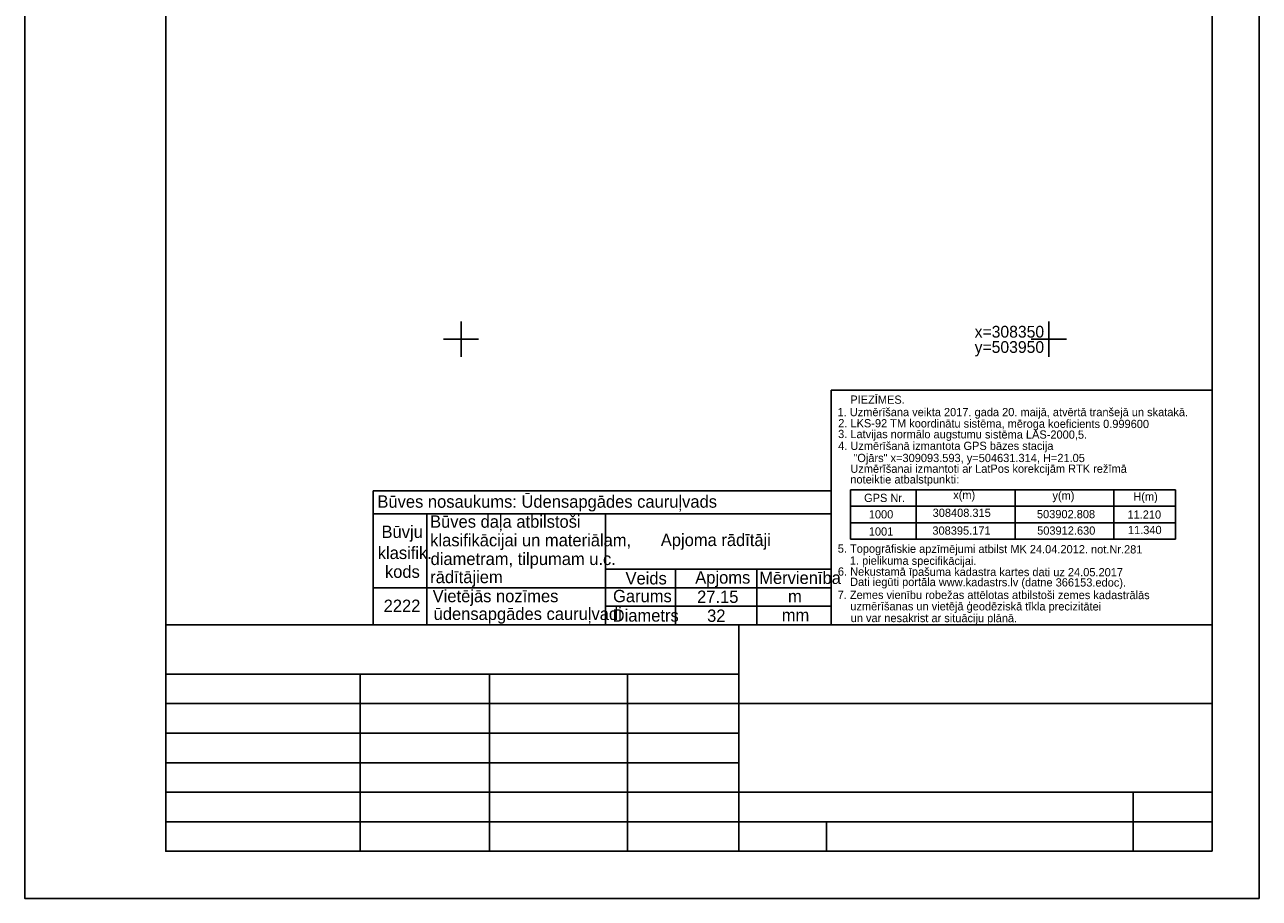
# Model space of a CAD drawing. Extents: x 503863 to 503968, y 308302 to 308451.
# Drawn here: x 503862.9 to 503967.9, y 308302.5 to 308376.7 of the extents above; entities that cross this region are included whole.
import ezdxf

# ---------------------------------------------------------------- set-up
doc = ezdxf.new("R2010")
doc.units = 0
for name, color, linetype in [('GEOD_ELEM_####_####_#', 7, 'Continuous'), ('GEOD_KORD_####_TKST_#', 7, 'Continuous'), ('RAMI_PLAN_####_TKST_#', 7, 'Continuous')]:
    doc.layers.add(name, color=color, linetype=linetype)

msp = doc.modelspace()

# ---------------------------------------------------------------- linework, layer by layer
at = {"layer": 'GEOD_ELEM_####_####_#'}
for p, q in [((503900, 308351.5), (503900, 308350)), ((503950, 308351.5), (503950, 308350)), ((503898.5, 308350), (503900, 308350)), ((503900, 308350), (503900, 308348.5)), ((503900, 308350), (503901.5, 308350)), ((503948.5, 308350), (503950, 308350)), ((503950, 308350), (503950, 308348.5)), ((503950, 308350), (503951.5, 308350))]:
    msp.add_line(p, q, dxfattribs=at)
at = {"layer": 'RAMI_PLAN_####_TKST_#'}
for p, q in [((503963.89, 308443.52), (503963.89, 308306.47)), ((503931.47, 308345.66), (503931.47, 308325.71)), ((503931.47, 308345.66), (503963.89, 308345.66)), ((503931.47, 308325.71), (503931.47, 308340.26)), ((503892.54, 308337.11), (503892.54, 308325.71)), ((503892.54, 308337.11), (503931.47, 308337.11)), ((503960.77, 308337.2), (503933.12, 308337.2)), ((503933.12, 308333), (503933.12, 308337.2)), ((503938.72, 308333), (503938.72, 308337.2)), ((503947.12, 308333), (503947.12, 308337.2)), ((503955.52, 308333), (503955.52, 308337.2)), ((503960.77, 308333), (503960.77, 308337.2)), ((503960.77, 308335.8), (503933.12, 308335.8)), ((503892.54, 308335.16), (503931.47, 308335.16)), ((503897.09, 308335.16), (503897.09, 308325.71)), ((503912.3, 308335.16), (503912.3, 308325.71)), ((503960.77, 308334.4), (503933.12, 308334.39)), ((503960.77, 308333), (503933.12, 308333)), ((503912.3, 308330.44), (503931.47, 308330.44)), ((503918.23, 308330.44), (503918.23, 308325.71)), ((503925.17, 308330.44), (503925.17, 308325.71)), ((503892.54, 308328.86), (503931.47, 308328.86)), ((503912.3, 308327.29), (503931.47, 308327.29)), ((503874.89, 308325.71), (503963.89, 308325.71)), ((503923.64, 308325.71), (503923.64, 308306.47)), ((503874.89, 308321.52), (503923.64, 308321.52)), ((503891.43, 308306.48), (503891.43, 308321.52)), ((503902.42, 308306.47), (503902.41, 308321.52)), ((503914.15, 308306.48), (503914.15, 308321.52)), ((503874.89, 308319.02), (503923.64, 308319.02)), ((503923.64, 308319.02), (503963.89, 308319.02)), ((503874.89, 308316.51), (503923.64, 308316.51)), ((503874.89, 308314), (503923.64, 308314)), ((503874.89, 308311.49), (503963.89, 308311.49)), ((503957.16, 308306.47), (503957.16, 308311.49)), ((503874.89, 308308.98), (503963.89, 308308.98)), ((503931.08, 308306.47), (503931.08, 308308.98))]:
    msp.add_line(p, q, dxfattribs=at)
for points in [[(503967.89, 308302.47), (503862.89, 308302.47), (503862.89, 308450.97), (503967.89, 308450.97)], [(503963.89, 308306.47), (503874.89, 308306.47), (503874.89, 308446.97), (503963.89, 308446.97)]]:
    msp.add_lwpolyline(points, close=True, dxfattribs=at)

# ---------------------------------------------------------------- texts
at = {"layer": 'GEOD_KORD_####_TKST_#'}
for s, p in [('x=308350', (503943.68, 308350.13)), ('y=503950', (503943.68, 308348.83))]:
    msp.add_text(s, height=1, dxfattribs=at).set_placement(p)
at = {"layer": 'RAMI_PLAN_####_TKST_#'}
for s, rotation, p in [('PIEZĪMES.', 359.9577, (503933.11, 308344.51)), ('1. Uzmērīšana veikta 2017. gada 20. maijā, atvērtā tranšejā un skatakā.', 359.9998, (503932.02, 308343.45)), ('2. LKS-92 TM koordinātu sistēma, mēroga koeficients 0.999600', 359.8453, (503932.08, 308342.51)), ('3. Latvijas normālo augstumu sistēma LAS-2000,5.', 359.8453, (503932.07, 308341.59)), ('4. Uzmērīšanā izmantota GPS bāzes stacija', 0.0005, (503932.07, 308340.58)), ('     "Ojārs" x=309093.593, y=504631.314, H=21.05', 0.0005, (503932.07, 308339.55)), ('    Uzmērīšanai izmantoti ar LatPos korekcijām RTK režīmā', 0.0005, (503932.07, 308338.64)), ('    noteiktie atbalstpunkti:', 0.0005, (503932.07, 308337.73)), ('5. Topogrāfiskie apzīmējumi atbilst MK 24.04.2012. not.Nr.281', 359.8453, (503932.04, 308331.85)), ('1. pielikuma specifikācijai.', 359.8453, (503933.07, 308330.83)), ('6. Nekustamā īpašuma kadastra kartes dati uz 24.05.2017', 359.8453, (503932.05, 308329.9)), ('      Dati iegūti portāla www.kadastrs.lv (datne 366153.edoc).', 359.8453, (503931.53, 308329.03)), ('7. Zemes vienību robežas attēlotas atbilstoši zemes kadastrālās ', 359.9577, (503932.03, 308327.92)), ('uzmērīšanas un vietējā ģeodēziskā tīkla precizitātei', 359.9577, (503933.11, 308326.95)), ('un var nesakrist ar situāciju plānā.', 359.9577, (503933.14, 308325.95))]:
    msp.add_text(s, height=0.7, rotation=rotation, dxfattribs=at).set_placement(p)
for s, height, p in [('Būves nosaukums: Ūdensapgādes cauruļvads', 1.05, (503892.89, 308335.67)), ('GPS Nr.', 0.7, (503934.28, 308336.16)), ('x(m)', 0.7, (503941.86, 308336.41)), ('y(m)', 0.7, (503950.3, 308336.35)), ('H(m)', 0.7, (503957.18, 308336.27)), ('Būves daļa atbilstoši', 1.05, (503897.37, 308333.97)), ('1000', 0.7, (503934.68, 308334.76)), ('308408.315', 0.7, (503940.11, 308334.89)), ('503902.808', 0.7, (503948.98, 308334.78)), ('11.210', 0.7, (503956.68, 308334.74)), ('Būvju', 1.05, (503893.24, 308333.1)), ('1001', 0.7, (503934.68, 308333.3)), ('308395.171', 0.7, (503940.09, 308333.38)), ('503912.630', 0.7, (503949, 308333.38)), ('11.340', 0.7, (503956.72, 308333.43)), ('klasifikācijai un materiālam,', 1.05, (503897.38, 308332.39)), ('Apjoma rādītāji', 1.05, (503916.99, 308332.41)), ('klasifik.', 1.05, (503892.92, 308331.31)), ('diametram, tilpumam u.c.', 1.05, (503897.41, 308330.8)), ('kods', 1.05, (503893.53, 308329.71)), ('rādītājiem', 1.05, (503897.38, 308329.26)), ('Veids', 1.05, (503913.99, 308329.15)), ('Apjoms', 1.05, (503919.92, 308329.22)), ('Mērvienība', 1.05, (503925.36, 308329.19)), ('Vietējās nozīmes', 1.05, (503897.59, 308327.64)), ('Garums', 1.05, (503912.93, 308327.64)), ('27.15', 1.05, (503920.08, 308327.58)), ('m', 1.05, (503927.81, 308327.62)), ('2222', 1.05, (503893.42, 308326.81)), ('ūdensapgādes cauruļvadi', 1.05, (503897.67, 308326.13)), ('Diametrs', 1.05, (503912.9, 308325.99)), ('32', 1.05, (503920.93, 308325.97)), ('mm', 1.05, (503927.28, 308326.02))]:
    msp.add_text(s, height=height, dxfattribs=at).set_placement(p)

doc.saveas('drawing.dxf')
